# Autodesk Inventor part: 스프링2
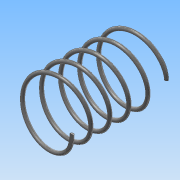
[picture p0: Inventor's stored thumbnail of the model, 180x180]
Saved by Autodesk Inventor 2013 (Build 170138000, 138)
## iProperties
Created: 2015-11
Part Number: 스프링2
Material: 강철, 탄소
Document SubType Name: Modeling
Designer: Administrator
Density: 7.87 g/cm^3
Mass: 1.54072 g
Surface Area: 7.8932 cm^2
Volume: 0.195771 cm^3
Author: Administrator
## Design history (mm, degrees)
sketch "스케치1"
  geometry: L1 (8, 26)-(0, 26); L2 (0, 26)-(0, 0); L3 (0, 0)-(8, 0); L4 (8, 0)-(8, 26); C1 r 0.5 at (8, 0)
  constraints: 8 end point, 2 parallel, 1 centre point, 1 coincident, 1 horizontal, 1 perpendicular
  dimensions: "d0" = 16 diameter of L4 L2; "d2" = 26 distance between parallel lines of L3 L1 (derived); "d3" = 1 diameter of C1
feature "코일1" sketch "스케치1" pitch "d4" = 10; turns "d6" = 5; dims "d5" = 26 (= d2), "d7" = 0, angle "d8" = 90 deg, angle "d9" = 90 deg, "d10" = 0, "d11" = 0
sketch "스케치2"
  geometry: L1 (0, 10)-(26, 10); L2 (26, 10)-(26, -10); L3 (26, -10)-(0, -10); L4 (0, -10)-(0, 10); 4 further points
  constraints: 8 end point, 2 coincident, 2 midpoint, 2 parallel, 1 horizontal, 1 perpendicular
  dimensions: "d12" = 20 distance between parallel lines of L3 L1
extrude "돌출1" sketch "스케치2" stored distance "d15" = 0; taper "d16" = 0 deg
node "솔리드1"
